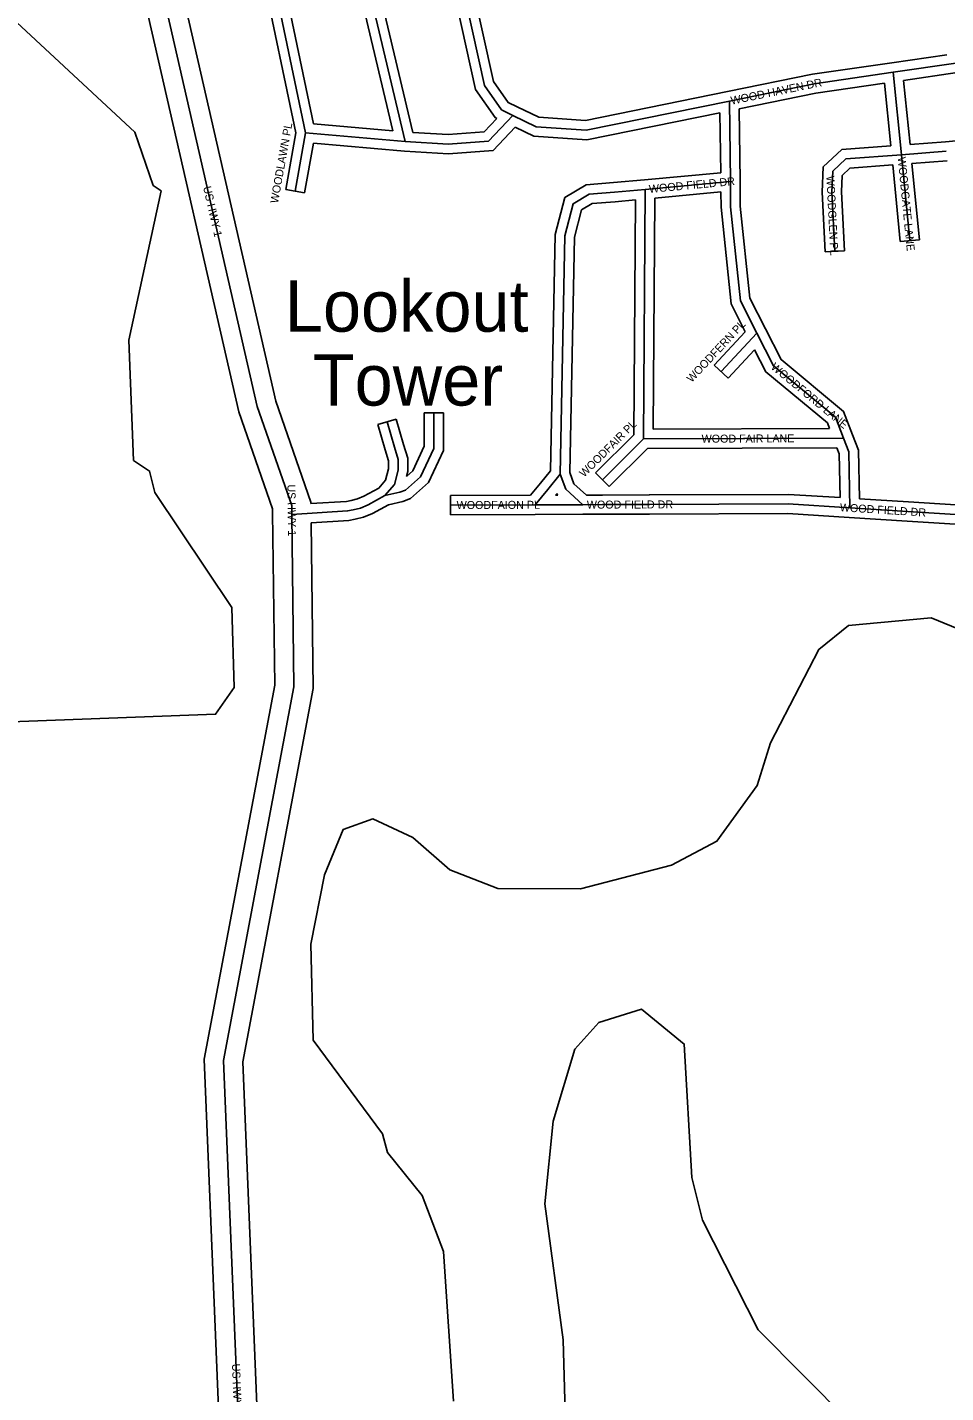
# Model space of a CAD drawing. Extents: x 457167 to 656239, y 1787309 to 1969297.
# Drawn here: x 571788 to 574657, y 1887885 to 1892149 of the extents above; entities that cross this region are included whole.
import ezdxf

# ---------------------------------------------------------------- set-up
doc = ezdxf.new("R2010")
doc.units = 0
for name, color, linetype in [('Level 13', 7, 'Continuous'), ('Level 14', 7, 'Continuous'), ('Level 31', 7, 'Continuous'), ('Level 32', 7, 'Continuous'), ('Level 34', 7, 'Continuous'), ('Level 57', 7, 'Continuous'), ('Level 7', 7, 'Continuous')]:
    doc.layers.add(name, color=color, linetype=linetype)

msp = doc.modelspace()

# ---------------------------------------------------------------- linework, layer by layer
at = {"layer": 'Level 13'}
msp.add_line((572614.488, 1890627.779), (572614.143, 1890655.756), dxfattribs=at)
for points in [[(572614.143, 1890655.756), (572506.712, 1890964.73), (572226.446, 1892190.831), (572202.075, 1892382.525), (572086.293, 1892791.52), (572004.598, 1893366.985), (572019.78, 1893611.317)], [(572485.101, 1886875.279), (572401.296, 1888922.399), (572621.138, 1890089.189), (572614.488, 1890627.779)]]:
    msp.add_lwpolyline(points, dxfattribs=at)
at = {"layer": 'Level 14'}
for p, q in [((572674.079, 1890661.551), (572674.021, 1890666.249)), ((572554.415, 1890633.199), (572554.267, 1890645.263))]:
    msp.add_line(p, q, dxfattribs=at)
for points in [[(572554.268, 1890645.263), (572448.955, 1890948.141), (572167.296, 1892180.337), (572143.119, 1892370.502), (572027.457, 1892779.075), (571944.334, 1893364.604), (571959.895, 1893615.038)], [(572674.02, 1890666.249), (572564.469, 1890981.317), (572285.596, 1892201.326), (572261.031, 1892394.547), (572145.129, 1892803.965), (572064.862, 1893369.366), (572079.665, 1893607.596)], [(572425.15, 1886872.825), (572341.065, 1888926.783), (572561.067, 1890094.425), (572554.415, 1890633.197)], [(572545.052, 1886877.733), (572461.527, 1888918.015), (572681.208, 1890083.953), (572674.819, 1890601.481)]]:
    msp.add_lwpolyline(points, dxfattribs=at)
at = {"layer": 'Level 31'}
for p, q in [((574688.122, 1892036.983), (574492.802, 1892008.321)), ((574492.802, 1892008.321), (574245.949, 1891972.864)), ((574492.802, 1892008.321), (574518.631, 1891751.171)), ((573981.245, 1891918.54), (574245.949, 1891972.864)), ((573984.506, 1891667.621), (573981.245, 1891918.54)), ((572657.785, 1891819.673), (572624.936, 1891636.835)), ((572657.785, 1891819.673), (572968.419, 1891792.066)), ((574518.631, 1891751.171), (574658.897, 1891761.771)), ((574518.631, 1891751.171), (574545.072, 1891482.746)), ((573718.593, 1891642.755), (573713.047, 1890863.485)), ((573984.506, 1891667.621), (573718.593, 1891642.755)), ((574067.412, 1891193.25), (573955.206, 1891073.496)), ((573713.047, 1890863.485), (574337.96, 1890865.74)), ((573713.047, 1890863.485), (573584.602, 1890736.132)), ((573374.217, 1890657.691), (573110.575, 1890656.826)), ((573523.687, 1890658.086), (573374.217, 1890657.691)), ((573584.748, 1890658.313), (573523.687, 1890658.086)), ((573731.356, 1890658.715), (573584.748, 1890658.313)), ((574538.762, 1890636.931), (574357.834, 1890648.239)), ((574870.73, 1890616.203), (574538.762, 1890636.931))]:
    msp.add_line(p, q, dxfattribs=at)
for points in [[(572968.419, 1891792.066), (572661.59, 1893088.043), (572631.816, 1893282.295), (572619.401, 1893417.596), (572628.527, 1893516.486)], [(572341.633, 1893207.311), (572345.05, 1893171.666), (572446.043, 1892831.071), (572657.785, 1891819.673)], [(573013.166, 1892887.616), (573216.54, 1891967.149), (573269.795, 1891890.666), (573305.056, 1891873.496)], [(573305.056, 1891873.496), (573378.12, 1891838.423), (573533.603, 1891827.531), (573981.245, 1891918.54)], [(573305.056, 1891873.496), (573229.191, 1891793.665), (573103.238, 1891784.128), (572968.419, 1891792.066)], [(574310.941, 1891449.078), (574301.491, 1891634.556), (574304.178, 1891699.278), (574344.968, 1891737.734), (574518.631, 1891751.171)], [(573718.593, 1891642.755), (573622.216, 1891633.878), (573543.016, 1891627.509), (573493.34, 1891597.801), (573467.358, 1891497.494), (573452.662, 1890753.154)], [(574067.412, 1891193.25), (574015.8, 1891294.456), (573985.285, 1891588.708), (573984.506, 1891667.621)], [(574337.96, 1890865.74), (574312.98, 1890931.25), (574119.025, 1891092.043), (574067.412, 1891193.25)], [(572905.519, 1890686.376), (572934.854, 1890720.856), (572946.722, 1890765.921), (572946.796, 1890799.376), (572935.115, 1890837.583), (572912.077, 1890916.546)], [(573016.958, 1890745.399), (573057.862, 1890833.672), (573058.11, 1890944.583)], [(574357.834, 1890648.239), (574354.402, 1890822.794), (574337.96, 1890865.74)], [(572905.519, 1890686.376), (572952.292, 1890697.181), (572970.115, 1890703.686), (573016.958, 1890745.399)], [(573452.662, 1890753.154), (573414.713, 1890705.965), (573374.217, 1890657.691)], [(573452.662, 1890753.154), (573470.367, 1890706.205), (573523.687, 1890658.086)], [(572614.488, 1890627.779), (572788.698, 1890638.637), (572806.197, 1890641.871), (572829.424, 1890647.273), (572852.98, 1890657.402), (572905.519, 1890686.376)], [(574357.834, 1890648.239), (574164.821, 1890660.301), (573731.356, 1890658.715)]]:
    msp.add_lwpolyline(points, dxfattribs=at)
at = {"layer": 'Level 32'}
for p, q in [((574660.695, 1892063.279), (574488.446, 1892038.003)), ((574488.537, 1892038.016), (574240.796, 1892002.432)), ((573975.215, 1891947.927), (574240.797, 1892002.432)), ((574466.081, 1891974.173), (574251.102, 1891943.294)), ((574466.081, 1891974.173), (574485.715, 1891778.713)), ((574692.478, 1892007.3), (574525.518, 1891982.799)), ((574525.518, 1891982.799), (574545.557, 1891783.291)), ((574011.566, 1891894.135), (574251.101, 1891943.294)), ((574014.505, 1891668.01), (574011.566, 1891894.135)), ((572682.592, 1891847.586), (572929.643, 1891825.631)), ((573954.15, 1891694.912), (573951.72, 1891881.921)), ((572627.225, 1891819.235), (572595.409, 1891642.14)), ((572682.461, 1891787.36), (572654.465, 1891631.529)), ((572682.461, 1891787.36), (572966.209, 1891762.143)), ((574545.557, 1891783.291), (574656.637, 1891791.686)), ((574491.656, 1891718.992), (574515.217, 1891479.804)), ((574551.497, 1891723.568), (574661.159, 1891731.856)), ((574551.497, 1891723.567), (574574.929, 1891485.686)), ((573954.15, 1891694.912), (573715.8, 1891672.625)), ((572654.465, 1891631.529), (572595.409, 1891642.14)), ((573954.83, 1891634.713), (573748.4, 1891615.409)), ((573688.357, 1891609.841), (573683.135, 1890876.074)), ((573748.4, 1891615.409), (573743.264, 1890893.594)), ((574574.929, 1891485.686), (574515.217, 1891479.804)), ((574280.98, 1891447.552), (574340.902, 1891450.605)), ((574031.117, 1891198.387), (573933.315, 1891094.008)), ((574060.095, 1891141.562), (573977.099, 1891052.984)), ((573977.099, 1891052.984), (573933.315, 1891094.008)), ((572883.277, 1890908.142), (572940.876, 1890924.948)), ((573028.11, 1890944.65), (573088.11, 1890944.516)), ((573683.136, 1890876.074), (573563.48, 1890757.436)), ((573743.263, 1890893.593), (574294.473, 1890895.582)), ((573725.445, 1890833.527), (573605.725, 1890714.828)), ((573725.445, 1890833.528), (574317.351, 1890835.663)), ((572972.493, 1890745.974), (572992.356, 1890763.661)), ((573605.725, 1890714.828), (573563.48, 1890757.436)), ((573360.188, 1890687.646), (573110.478, 1890686.826)), ((573110.675, 1890626.825), (573110.478, 1890686.826)), ((573443.125, 1890693.421), (573438.653, 1890687.861)), ((573445.893, 1890687.881), (573438.653, 1890687.861)), ((573584.636, 1890688.313), (573535.176, 1890688.128)), ((573731.274, 1890688.715), (573584.665, 1890688.313)), ((574540.633, 1890666.873), (574387.285, 1890676.456)), ((574840.8, 1890648.131), (574540.631, 1890666.874)), ((573374.315, 1890627.691), (573110.675, 1890626.825)), ((573523.767, 1890628.085), (573374.296, 1890627.691)), ((573584.86, 1890628.312), (573523.8, 1890628.085)), ((573731.439, 1890628.715), (573584.83, 1890628.312)), ((574536.891, 1890606.989), (574355.963, 1890618.296)), ((574840.84, 1890588.009), (574536.893, 1890606.988))]:
    msp.add_line(p, q, dxfattribs=at)
for points in [[(572929.643, 1891825.631), (572632.119, 1893082.306), (572602.025, 1893278.648), (572589.274, 1893417.605), (572596.571, 1893496.666)], [(572992.47, 1891820.702), (572691.061, 1893093.781), (572661.609, 1893285.941), (572649.529, 1893417.589), (572654.765, 1893474.328)], [(572311.596, 1893206.272), (572315.463, 1893165.918), (572416.93, 1892823.721), (572627.225, 1891819.235)], [(572371.672, 1893208.35), (572374.637, 1893177.416), (572475.155, 1892838.421), (572682.593, 1891847.586)], [(572983.873, 1892881.143), (573188.527, 1891954.879), (573249.639, 1891867.112), (573255.084, 1891864.46)], [(573048.916, 1892864.871), (573244.553, 1891979.42), (573289.952, 1891914.219), (573318.19, 1891900.469)], [(573318.039, 1891900.541), (573385.935, 1891867.95), (573531.626, 1891857.744), (573975.268, 1891947.938)], [(573255.085, 1891864.46), (573215.405, 1891822.707), (573102.985, 1891814.195), (572992.47, 1891820.701)], [(573311.761, 1891836.999), (573370.305, 1891808.896), (573535.579, 1891797.319), (573951.719, 1891881.921)], [(573311.761, 1891836.999), (573242.979, 1891764.621), (573103.49, 1891754.061), (572966.21, 1891762.143)], [(574280.98, 1891447.552), (574271.459, 1891634.415), (574274.71, 1891712.728), (574332.095, 1891766.829), (574485.715, 1891778.713)], [(574656.637, 1891791.686), (574722.584, 1891797.208), (574797.252, 1891742.626), (574811.774, 1891660.302), (574809.43, 1891474.942)], [(574340.902, 1891450.605), (574331.523, 1891634.697), (574333.645, 1891685.828), (574357.841, 1891708.639), (574491.656, 1891718.993)], [(573715.841, 1891672.628), (573619.638, 1891663.768), (573533.63, 1891656.851), (573467.385, 1891617.233), (573437.434, 1891501.606), (573422.87, 1890763.979)], [(574031.116, 1891198.388), (573986.535, 1891285.803), (573955.3, 1891587.01), (573954.83, 1891634.712)], [(574094.139, 1891206.88), (574045.065, 1891303.108), (574015.271, 1891590.407), (574014.505, 1891667.916)], [(573688.358, 1891609.841), (573624.794, 1891603.988), (573552.403, 1891598.166), (573519.297, 1891578.368), (573497.283, 1891493.381), (573482.771, 1890758.335)], [(574365.991, 1890876.428), (574338.2, 1890949.311), (574142.939, 1891111.188), (574094.139, 1891206.88)], [(574294.473, 1890895.583), (574287.759, 1890913.189), (574095.112, 1891072.898), (574060.095, 1891141.562)], [(572886.226, 1890709.996), (572907.581, 1890735.097), (572916.73, 1890769.837), (572916.786, 1890794.924), (572906.369, 1890828.996), (572883.277, 1890908.142)], [(572972.493, 1890745.974), (572976.715, 1890762.003), (572976.807, 1890803.826), (572963.861, 1890846.171), (572940.876, 1890924.948)], [(572992.356, 1890763.661), (573027.876, 1890840.317), (573028.11, 1890944.65)], [(573041.561, 1890727.135), (573087.848, 1890827.028), (573088.11, 1890944.516)], [(574387.286, 1890676.457), (574384.293, 1890828.625), (574365.976, 1890876.466)], [(574327.199, 1890680.211), (574324.51, 1890816.962), (574317.35, 1890835.663)], [(573422.87, 1890763.979), (573391.529, 1890725.008), (573360.187, 1890687.646)], [(573482.772, 1890758.336), (573495.87, 1890723.601), (573535.176, 1890688.128)], [(572674.079, 1890661.551), (572785.026, 1890668.466), (572800.07, 1890671.247), (572820.026, 1890675.889), (572839.78, 1890684.383), (572886.226, 1890709.995)], [(572916.346, 1890658.085), (572960.844, 1890668.365), (572985.786, 1890677.469), (573041.561, 1890727.135)], [(572674.819, 1890601.481), (572792.37, 1890608.807), (572812.324, 1890612.494), (572838.822, 1890618.658), (572866.18, 1890630.421), (572916.345, 1890658.085)], [(573443.125, 1890693.421), (573444.865, 1890688.809), (573445.893, 1890687.881)], [(574327.199, 1890680.211), (574165.703, 1890690.305), (573731.246, 1890688.716)], [(574355.962, 1890618.296), (574163.94, 1890630.296), (573731.465, 1890628.715)]]:
    msp.add_lwpolyline(points, dxfattribs=at)
at = {"layer": 'Level 7'}
for points in [[(571542.664, 1889973.07), (572376.399, 1890003.731), (572435.009, 1890086.904), (572427.495, 1890337.03), (572186.885, 1890696.276), (572170.435, 1890762.997), (572120.523, 1890796.507), (572105.058, 1891171.706), (572206.594, 1891638.219), (572181.613, 1891654.959), (572123.82, 1891821.882), (571591.863, 1892315.427)], [(574877.941, 1890195.767), (574611.505, 1890304.987), (574353.02, 1890280.833), (574261.09, 1890206.1), (574110.091, 1889914.811), (574067.982, 1889781.567), (573942.382, 1889606.891), (573800.4, 1889532.318), (573516.736, 1889458.212), (573258.312, 1889459.03), (573108.459, 1889517.869), (572992.075, 1889618.27), (572867.192, 1889677.05), (572775.39, 1889643.998), (572716.581, 1889502.444), (572674.214, 1889285.828), (572681.568, 1888985.721), (572897.395, 1888693.226), (572913.877, 1888634.836), (573021.82, 1888501.093), (573087.954, 1888325.84), (573119.8, 1887858.869)]]:
    msp.add_lwpolyline(points, dxfattribs=at)
msp.add_lwpolyline([(574266.029, 1886554.742), (574416.181, 1886587.595), (574541.482, 1886662.198), (574725.861, 1886970.048), (574759.57, 1887086.661), (574760.128, 1887261.726), (574511.378, 1887679.362), (574353.374, 1887796.563), (574070.855, 1888080.916), (573896.877, 1888423.262), (573863.955, 1888556.736), (573840.289, 1888973.655), (573707.265, 1889082.456), (573573.753, 1889041.193), (573498.463, 1888958.061), (573431.055, 1888733.204), (573405.198, 1888474.847), (573462.205, 1888049.528), (573477.182, 1887524.276), (573543.056, 1887273.991), (573625.93, 1887115.297), (573850.028, 1886814.473), (574049.614, 1886655.461), (574266.029, 1886554.742)], close=True, dxfattribs=at)

# ---------------------------------------------------------------- texts
at = {"layer": 'Level 34'}
for s, rotation, p in [('WOOD HAVEN DR', 11.596922, (573988.377, 1891907.244)), ('WOODLAWN PL', 79.814164, (572571.411, 1891597.974)), ('WOODGATE LANE', 275.625044, (574506.91, 1891742.677)), ('WOOD FIELD DR', 5.341419, (573731.353, 1891631.395)), ('WOODGLEN PL', 272.915836, (574284.116, 1891684.46)), ('US HWY 1', 282.874911, (572337.34, 1891649.606)), ('WOODFERN PL', 46.862492, (573863.542, 1891037.846)), ('WOODFORD LANE', 320.339719, (574108.734, 1891084.341)), ('WOODFAIR PL', 44.75445, (573527.536, 1890742.145)), ('WOOD FAIR LANE', 0.205967, (573894.684, 1890851.642)), ('US HWY 1', 270.705453, (572600.836, 1890721.223)), ('WOODFAION PL', 0.187461, (573129.525, 1890644.389)), ('WOOD FIELD DR', 0.156222, (573536.197, 1890645.681)), ('WOOD FIELD DR', 356.423208, (574325.865, 1890637.714)), ('US HWY 1', 272.343497, (572427.579, 1887974.799))]:
    msp.add_text(s, height=25, rotation=rotation, dxfattribs=at).set_placement(p)
at = {"layer": 'Level 57'}
for s, p in [('Lookout', (572592.818, 1891198.309)), ('Tower', (572680.068, 1890967.702))]:
    msp.add_text(s, height=160, dxfattribs=at).set_placement(p)

doc.saveas('drawing.dxf')
